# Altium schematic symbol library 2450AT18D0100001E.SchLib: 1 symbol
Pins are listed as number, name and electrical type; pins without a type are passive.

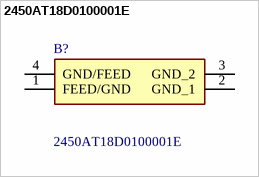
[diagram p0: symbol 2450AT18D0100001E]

## 2450AT18D0100001E
designator B?
2.4GHz Chip RF Antenna 2.4GHz ~ 2.5GHz 1.5dBi Solder Surface Mount; Manufacturer_Name: JOHANSON TECHNOLOGY; Geometry.Height: 1.3mm
footprint 2450AT18D0100001E
pins: 1 FEED/GND, 2 GND_1, 3 GND_2, 4 GND/FEED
